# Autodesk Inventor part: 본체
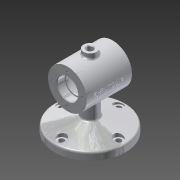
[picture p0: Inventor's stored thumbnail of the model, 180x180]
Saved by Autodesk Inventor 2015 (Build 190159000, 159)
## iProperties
Created: 2018-12
Part Number: 본체
Material: 알루미늄 6061
Document SubType Name: Modeling
Designer: CAD02
Density: 2.7 g/cm^3
Appearance: 알루미늄 - 평지
Mass: 685.089 g
Surface Area: 555.482 cm^2
Volume: 253.737 cm^3
Author: CAD02
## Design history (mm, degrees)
sketch "스케치1"
  geometry: C1 r 55 at (0, 0); 1 further point
  constraints: 1 centre point, 1 coincident
  dimensions: "d0" = 110 diameter of C1
extrude "돌출1" new body sketch "스케치1" distance "d1" = 11; taper "d2" = 0 deg
sketch "스케치2"
  geometry: L1 (-55, 0)-(-55, 11) reference; L2 (-55, 11)-(55, 11) reference; L3 (55, 11)-(55, 0) reference; L4 (55, 0)-(-55, 0) reference; L5 (-55, 11)-(0, 25.737); L6 (0, 25.737)-(0, 11); 1 further point
  constraints: 4 end point, 1 midpoint, 1 vertical
  dimensions: "d3" = 75 deg angle of L1 L5
revolve "회전1" sketch "스케치2" stored, may be unused: angle "d4" = 90 deg
sketch "스케치4"
  geometry: C1 r 55 at (0, 0) reference; C2 r 12 at (0, 0)
  constraints: 1 centre point, 1 coincident
  dimensions: "d5" = 24 diameter of C2
extrude "돌출2" join sketch "스케치4" distance "d6" = 75; taper "d7" = 0 deg
sketch "스케치6"
  geometry: L1 (-12, 22.522)-(-12, 75) reference; L2 (-12, 75)-(12, 75) reference; L3 (12, 75)-(12, 22.522) reference; L4 (12, 22.522)-(55, 11) reference; L5 (55, 11)-(55, 0) reference; L6 (55, 0)-(-55, 0) reference; L7 (-55, 0)-(-55, 11) reference; L8 (-55, 11)-(-12, 22.522) reference; L9 (-35, 75)-(35, 75); L10 (35, 75)-(35, 105); L11 (35, 105)-(-35, 105); L12 (-35, 105)-(-35, 75); 2 further points
  constraints: 8 end point, 3 perpendicular, 2 midpoint, 1 horizontal
  dimensions: "d8" = 70 distance between parallel lines of L10 L12; "d9" = 30 distance between parallel lines of L11 L9
revolve "회전2" sketch "스케치6" stored, may be unused: angle "d10" = 90 deg
sketch "스케치7"
  geometry: L1 (-12, 45)-(-35, 45) reference; L2 (-35, 45)-(-35, 105) reference; L3 (-35, 105)-(35, 105) reference; L4 (35, 105)-(35, 45) reference; L5 (35, 45)-(12, 45) reference; L6 (12, 45)-(12, 22.522) reference; L7 (12, 22.522)-(55, 11) reference; L8 (55, 11)-(55, 0) reference; L9 (55, 0)-(-55, 0) reference; L10 (-55, 0)-(-55, 11) reference; L11 (-55, 11)-(-12, 22.522) reference; L12 (-12, 22.522)-(-12, 45) reference; L13 (-35, 75)-(-23, 75); L14 (-23, 75)-(-23, 90.7); L15 (-23.3, 91)-(-35, 91); L16 (-35, 91)-(-35, 75); L17 (-23, 75)-(-20, 75); L18 (-20, 75)-(-20, 89); L19 (-20, 89)-(-23, 89); L20 (-23, 89)-(-23, 75); L21 (-20, 75)-(20, 75); L22 (20, 75)-(20, 97); L23 (17, 100)-(-17, 100); L24 (-20, 97)-(-20, 75); L25 (20, 75)-(23, 75); L26 (23, 75)-(23, 89); L27 (23, 89)-(20, 89); L28 (20, 89)-(20, 75); L29 (23, 75)-(35, 75); L30 (35, 75)-(35, 91); L31 (35, 91)-(23.3, 91); L32 (23, 90.7)-(23, 75); A1 r 3 centre (-17, 97) between (-17, 100) and (-20, 97); A2 r 3 centre (17, 97) between (20, 97) and (17, 100); A3 r 0.3 centre (-23.3, 90.7) between (-23, 90.7) and (-23.3, 91); A4 r 0.3 centre (23.3, 90.7) between (23.3, 91) and (23, 90.7); 1 further point
  constraints: 40 end point, 10 parallel, 8 point on circle, 8 tangent, 5 horizontal, 5 perpendicular, 4 centre point, 2 equal radius, 1 midpoint
  dimensions: "d11" = 12 distance between parallel lines of L14 L16; "d12" = 16 distance between parallel lines of L13 L15; "d13" = 3 distance between parallel lines of L18 L20; "d14" = 14 distance between parallel lines of L17 L19; "d15" = 40 distance between parallel lines of L22 L24; "d16" = 25 distance between parallel lines of L21 L23; "d17" = 14 distance between parallel lines of L25 L27; "d18" = 3 distance between parallel lines of L26 L28; "d19" = 12 distance between parallel lines of L30 L32; "d20" = 16 distance between parallel lines of L29 L31; "d21" = 3 radius of A1; "d22" = 0.3 radius of A3
revolve "회전3" sketch "스케치7" stored, may be unused: angle "d23" = 90 deg
chamfer "모따기1" distance "d24" = 1; stored, may be unused: second distance "d25" = 2, angle "d26" = 45 deg
sketch "스케치8"
  geometry: C1 r 30 at (0, 0) reference; 2 further points
  constraints: 1 vertical alignment
  dimensions: "d27" = 23 distance of C1.centre point (0, 23)
hole "구멍1" sketch "스케치8" at (0, 23) diameter "d28" = 3.242; stored, may be unused: countersink angle "d32" = 90 deg, drill point angle "d34" = 118 deg; dims "d29" = 8, "d30" = 4, "d31" = 2, "d33" = 10
sketch "스케치9"
  geometry: C1 r 30 at (0, 0) reference; 2 further points
  constraints: 1 vertical alignment
  dimensions: "d38" = 23 distance of point (0, -23) C1.centre
hole "구멍2" sketch "스케치9" at (0, -23) diameter "d39" = 3.242; stored, may be unused: countersink angle "d43" = 90 deg, drill point angle "d45" = 118 deg; dims "d40" = 8, "d41" = 4, "d42" = 2, "d44" = 10
node "작업 평면1"
sketch "스케치10"
  geometry: L1 (30, -35)-(-30, -35) reference; C1 r 10 at (0, 0); 1 further point
  constraints: 1 centre point, 1 coincident
  dimensions: "d50" = 20 diameter of C1; "d51" = 35 distance from line of C1.centre L1
extrude "돌출3" join sketch "스케치10" stored distance "d52" = 75; taper "d53" = 0 deg
sketch "스케치11"
  geometry: C1 r 10 at (0, 0) reference
hole "구멍3" sketch "스케치11" at (0, 0) diameter "d54" = 10; stored, may be unused: countersink angle "d58" = 90 deg, drill point angle "d60" = 118 deg; dims "d55" = 8, "d56" = 4, "d57" = 2, "d59" = 10
fillet "모깎기1" dims "d61" = 3
chamfer "모따기2" distance "d62" = 1; stored, may be unused: second distance "d63" = 2, angle "d64" = 45 deg
sketch "스케치13"
  geometry: C1 r 55 at (0, 0) reference; C2 r 4.5 at (-44, 0); 1 further point
  constraints: 1 centre point, 1 coincident, 1 horizontal alignment
  dimensions: "d65" = 44 distance of C1.centre point (-44, 0); "d66" = 9 diameter of C2
extrude "돌출4" cut sketch "스케치13" stored distance "d67" = 75; taper "d68" = 0 deg
node "작업 평면2"
sketch "스케치16"
  geometry: C1 r 7 at (44, 0); 1 further point
  constraints: 1 centre point, 1 horizontal alignment
  dimensions: "d73" = 14 diameter of C1; "d74" = 44 distance of point (0, 0) C1.centre
extrude "돌출5" cut sketch "스케치16" stored distance "d75" = 14 (= d73); taper "d76" = 0 deg
node "작업 평면3"
sketch "스케치17" dims "d8" = 70, "d9" = 30
  geometry: L1 (-35, 45)-(-35, 105) reference; 2 further points
  constraints: 1 other
  dimensions: "d81" = 35 distance from line of point (0, 75) L1; "d82" = 30 vertical distance of L1.end point (0, 75)
feature "엠보싱1" sketch "스케치17" dims "d8" = 70, "d9" = 30, "d83" = 0.5, "d84" = 0
node "솔리드1"
pattern_circular "원형 패턴1" dims angle "d36" = 360 deg
pattern_circular "원형 패턴2" dims angle "d47" = 360 deg
pattern_circular "원형 패턴3" dims angle "d70" = 360 deg
pattern_circular "원형 패턴4" dims angle "d78" = 360 deg
node "절단 모서리 투영1"
node "절단 모서리 투영3"
node "절단 모서리 투영4"
other parameters: "d49" = 112
